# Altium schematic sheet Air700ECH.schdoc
size 284 x 172 mm
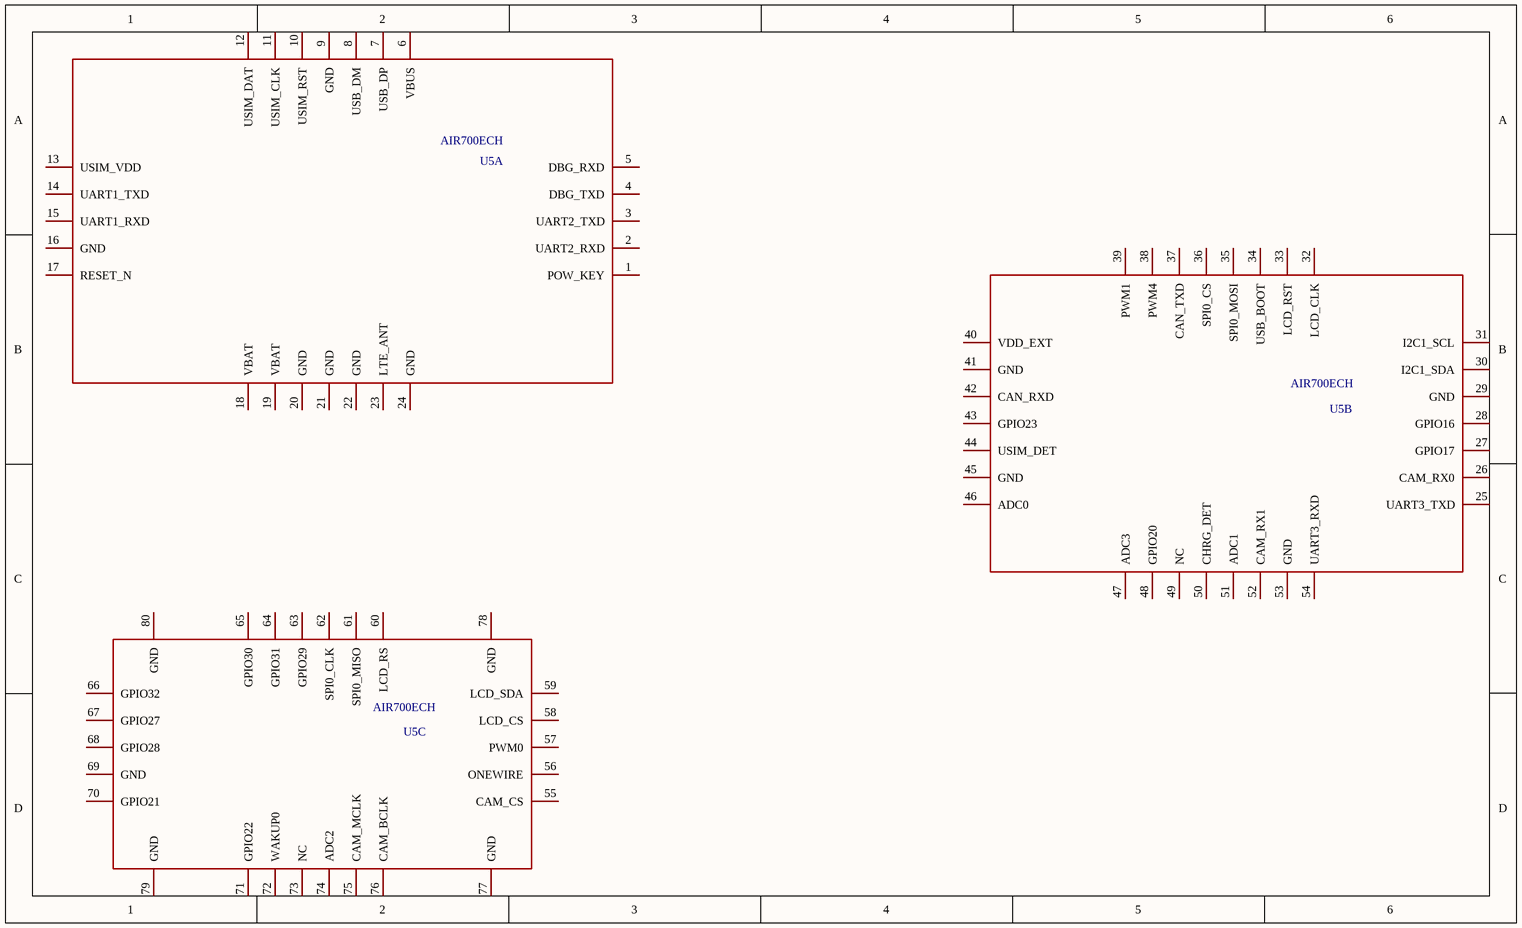
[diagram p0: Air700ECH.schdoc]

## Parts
U5  AIR700ECH  (parts A,B,C of 3)

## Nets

Not connected (* = marked no-connect by the designer): U5 1(POW_KEY) 2(UART2_RXD) 3(UART2_TXD) 4(DBG_TXD) 5(DBG_RXD) 6(VBUS) 7(USB_DP) 8(USB_DM) 9(GND) 10(USIM_RST) 11(USIM_CLK) 12(USIM_DAT) 13(USIM_VDD) 14(UART1_TXD) 15(UART1_RXD) 16(GND) 17(RESET_N) 18(VBAT) 19(VBAT) 20(GND) 21(GND) 22(GND) 23(LTE_ANT) 24(GND) 25(UART3_TXD) 26(CAM_RX0) 27(GPIO17) 28(GPIO16) 29(GND) 30(I2C1_SDA) 31(I2C1_SCL) 32(LCD_CLK) 33(LCD_RST) 34(USB_BOOT) 35(SPI0_MOSI) 36(SPI0_CS) 37(CAN_TXD) 38(PWM4) 39(PWM1) 40(VDD_EXT) 41(GND) 42(CAN_RXD) 43(GPIO23) 44(USIM_DET) 45(GND) 46(ADC0) 47(ADC3) 48(GPIO20) 49(NC) 50(CHRG_DET) 51(ADC1) 52(CAM_RX1) 53(GND) 54(UART3_RXD) 55(CAM_CS) 56(ONEWIRE) 57(PWM0) 58(LCD_CS) 59(LCD_SDA) 60(LCD_RS) 61(SPI0_MISO) 62(SPI0_CLK) 63(GPIO29) 64(GPIO31) 65(GPIO30) 66(GPIO32) 67(GPIO27) 68(GPIO28) 69(GND) 70(GPIO21) 71(GPIO22) 72(WAKUP0) 73(NC) 74(ADC2) 75(CAM_MCLK) 76(CAM_BCLK) 77(GND) 78(GND) 79(GND) 80(GND)

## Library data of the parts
U5 = AIR700ECH: Add into BOM: yes; Origin Footprint: AIR701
